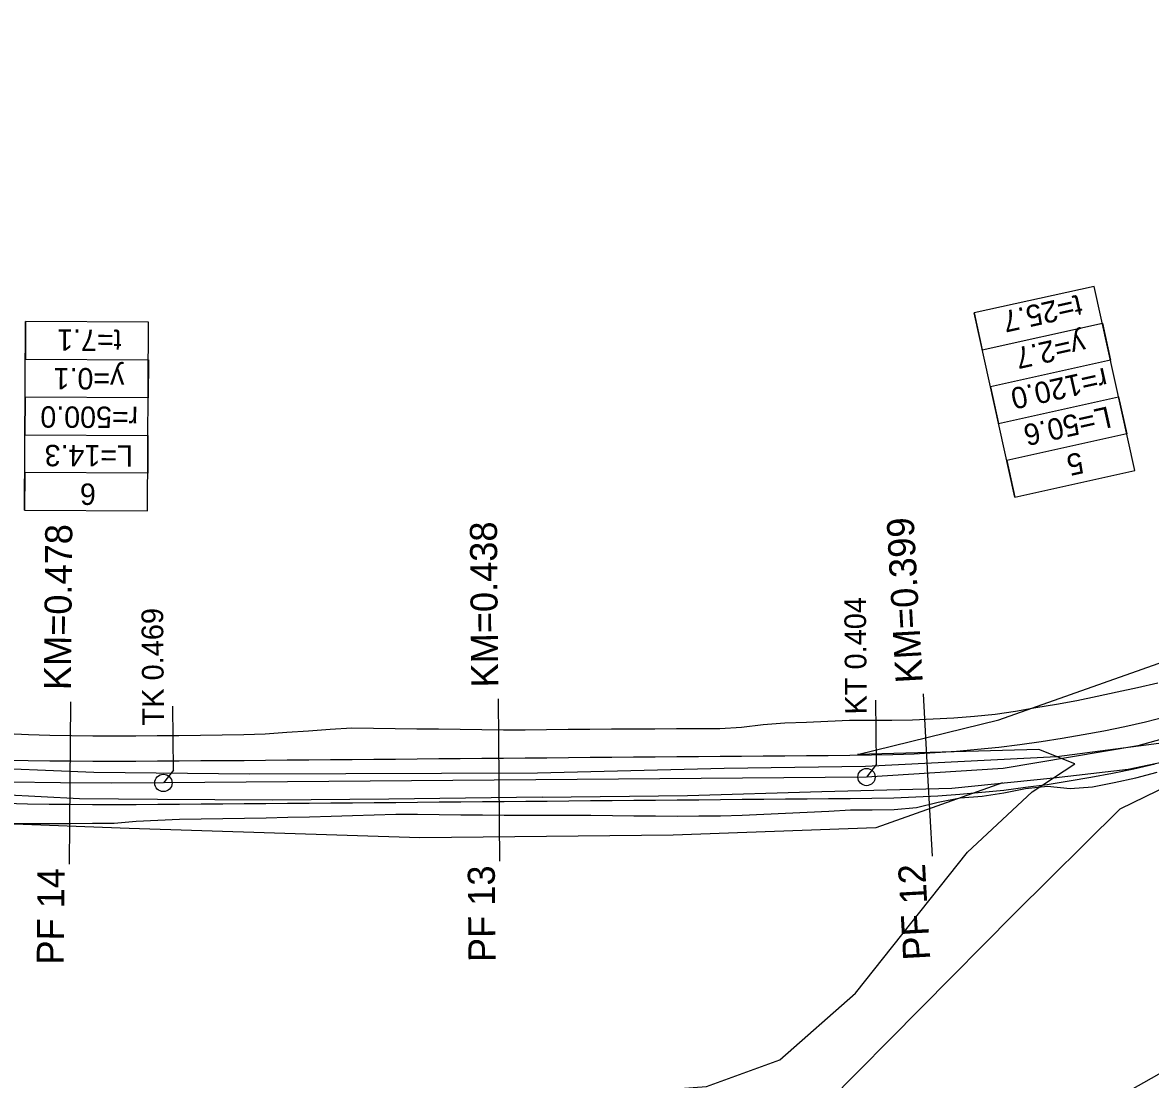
# Model space of a CAD drawing. Extents: x -478000 to -474772, y -1116940 to -1114124.
# Drawn here: x -477710.1 to -477605.9, y -1116669 to -1116571.3 of the extents above; entities that cross this region are included whole.
import ezdxf

# ---------------------------------------------------------------- set-up
doc = ezdxf.new("R2010")
doc.units = 0
for name, color, linetype in [('hrana_P', 7, 'Continuous'), ('L', 7, 'Continuous'), ('POLYGONY_SITUACE_PF', 7, 'Continuous'), ('POLYGONY_SITUACE_PF_POPISY', 7, 'Continuous'), ('POLYGONY_SITUACE_PO', 7, 'Continuous'), ('TABULKY', 7, 'Continuous')]:
    doc.layers.add(name, color=color, linetype=linetype)

msp = doc.modelspace()

# ---------------------------------------------------------------- linework, layer by layer
for points in [[(-477696.15, -1116640.39), (-477696.2, -1116634.49)], [(-477631.17, -1116639.83), (-477631.22, -1116633.94)], [(-477631.17, -1116639.83), (-477632.09, -1116641.03)], [(-477696.15, -1116640.39), (-477697.07, -1116641.58)]]:
    msp.add_lwpolyline(points)
at = {"layer": 'hrana_P'}
for p, q in [((-477607.2, -1116641.11), (-477605.22, -1116640.59)), ((-477617.39, -1116642.08), (-477615.36, -1116641.88)), ((-477615.36, -1116641.88), (-477613.26, -1116642.09)), ((-477613.26, -1116642.09), (-477611.21, -1116641.94)), ((-477611.21, -1116641.94), (-477609.2, -1116641.55)), ((-477609.2, -1116641.55), (-477607.2, -1116641.11)), ((-477625.46, -1116643.35), (-477623.44, -1116642.94)), ((-477623.44, -1116642.94), (-477621.4, -1116642.81)), ((-477621.4, -1116642.81), (-477619.39, -1116642.49)), ((-477619.39, -1116642.49), (-477617.39, -1116642.08)), ((-477631.57, -1116644.07), (-477629.52, -1116644.02)), ((-477629.52, -1116644.02), (-477627.48, -1116643.85)), ((-477627.48, -1116643.85), (-477625.46, -1116643.35)), ((-477701.61, -1116645.28), (-477699.6, -1116645.1)), ((-477699.6, -1116645.1), (-477697.58, -1116645.01)), ((-477697.58, -1116645.01), (-477695.58, -1116644.92)), ((-477695.58, -1116644.92), (-477693.58, -1116644.89)), ((-477693.58, -1116644.89), (-477691.58, -1116644.86)), ((-477691.58, -1116644.86), (-477689.58, -1116644.83)), ((-477689.58, -1116644.83), (-477687.58, -1116644.79)), ((-477687.58, -1116644.79), (-477685.58, -1116644.75)), ((-477685.58, -1116644.75), (-477683.58, -1116644.7)), ((-477683.58, -1116644.7), (-477681.58, -1116644.65)), ((-477681.58, -1116644.65), (-477679.58, -1116644.59)), ((-477679.58, -1116644.59), (-477677.58, -1116644.53)), ((-477677.58, -1116644.53), (-477675.58, -1116644.47)), ((-477675.58, -1116644.47), (-477673.58, -1116644.47)), ((-477673.58, -1116644.47), (-477671.58, -1116644.49)), ((-477671.58, -1116644.49), (-477669.58, -1116644.51)), ((-477669.58, -1116644.51), (-477667.58, -1116644.52)), ((-477667.58, -1116644.52), (-477665.58, -1116644.54)), ((-477665.58, -1116644.54), (-477663.58, -1116644.55)), ((-477663.58, -1116644.55), (-477661.58, -1116644.56)), ((-477661.58, -1116644.56), (-477659.58, -1116644.56)), ((-477659.58, -1116644.56), (-477657.58, -1116644.56)), ((-477657.58, -1116644.56), (-477655.58, -1116644.57)), ((-477655.58, -1116644.57), (-477653.58, -1116644.6)), ((-477653.58, -1116644.6), (-477651.58, -1116644.63)), ((-477651.58, -1116644.63), (-477649.58, -1116644.65)), ((-477649.58, -1116644.65), (-477647.58, -1116644.63)), ((-477647.58, -1116644.63), (-477645.58, -1116644.6)), ((-477645.58, -1116644.6), (-477643.58, -1116644.56)), ((-477643.58, -1116644.56), (-477641.58, -1116644.47)), ((-477641.58, -1116644.47), (-477639.58, -1116644.37)), ((-477639.58, -1116644.37), (-477637.58, -1116644.27)), ((-477637.58, -1116644.27), (-477635.58, -1116644.17)), ((-477635.58, -1116644.17), (-477633.58, -1116644.07)), ((-477633.58, -1116644.07), (-477631.57, -1116644.07)), ((-477711.68, -1116645.29), (-477709.67, -1116645.32)), ((-477709.67, -1116645.32), (-477707.66, -1116645.33)), ((-477707.66, -1116645.33), (-477705.64, -1116645.32)), ((-477705.64, -1116645.32), (-477703.62, -1116645.3)), ((-477703.62, -1116645.3), (-477701.61, -1116645.28))]:
    msp.add_line(p, q, dxfattribs=at)
for points in [[(-477607.04, -1116632.77), (-477605.18, -1116632.33)], [(-477612.66, -1116633.96), (-477610.78, -1116633.57)], [(-477610.78, -1116633.57), (-477608.92, -1116633.17)], [(-477608.92, -1116633.17), (-477607.04, -1116632.77)], [(-477618.32, -1116634.94), (-477616.43, -1116634.62)], [(-477616.43, -1116634.62), (-477614.54, -1116634.3)], [(-477614.54, -1116634.3), (-477612.66, -1116633.96)], [(-477627.85, -1116635.74), (-477625.94, -1116635.66)], [(-477625.94, -1116635.66), (-477624.03, -1116635.55)], [(-477624.03, -1116635.55), (-477622.12, -1116635.4)], [(-477622.12, -1116635.4), (-477620.21, -1116635.22)], [(-477620.21, -1116635.22), (-477618.32, -1116634.94)], [(-477604.39, -1116635.48), (-477606.31, -1116635.95)], [(-477685.65, -1116636.89), (-477683.65, -1116636.75)], [(-477683.65, -1116636.75), (-477681.65, -1116636.6)], [(-477681.65, -1116636.6), (-477679.65, -1116636.49)], [(-477679.65, -1116636.49), (-477677.65, -1116636.52)], [(-477677.65, -1116636.52), (-477675.65, -1116636.54)], [(-477675.65, -1116636.54), (-477673.65, -1116636.57)], [(-477673.65, -1116636.57), (-477671.65, -1116636.59)], [(-477671.65, -1116636.59), (-477669.65, -1116636.61)], [(-477669.65, -1116636.61), (-477667.65, -1116636.64)], [(-477667.65, -1116636.64), (-477665.65, -1116636.66)], [(-477665.65, -1116636.66), (-477663.65, -1116636.66)], [(-477663.65, -1116636.66), (-477661.65, -1116636.63)], [(-477661.65, -1116636.63), (-477659.65, -1116636.61)], [(-477659.65, -1116636.61), (-477657.65, -1116636.6)], [(-477657.65, -1116636.6), (-477655.65, -1116636.59)], [(-477655.65, -1116636.59), (-477653.65, -1116636.58)], [(-477653.65, -1116636.58), (-477651.65, -1116636.57)], [(-477651.65, -1116636.57), (-477649.65, -1116636.56)], [(-477649.65, -1116636.56), (-477647.65, -1116636.55)], [(-477647.65, -1116636.55), (-477645.65, -1116636.54)], [(-477645.65, -1116636.54), (-477643.65, -1116636.41)], [(-477643.65, -1116636.41), (-477641.65, -1116636.18)], [(-477641.65, -1116636.18), (-477639.65, -1116636.03)], [(-477639.65, -1116636.03), (-477637.65, -1116635.95)], [(-477637.65, -1116635.95), (-477635.65, -1116635.87)], [(-477635.65, -1116635.87), (-477633.66, -1116635.79)], [(-477633.66, -1116635.79), (-477631.67, -1116635.79)], [(-477631.67, -1116635.79), (-477629.76, -1116635.78)], [(-477629.76, -1116635.78), (-477627.85, -1116635.74)], [(-477608.22, -1116636.38), (-477610.15, -1116636.78)], [(-477606.31, -1116635.95), (-477608.22, -1116636.38)], [(-477711.52, -1116637.02), (-477709.53, -1116637.09)], [(-477709.53, -1116637.09), (-477707.55, -1116637.16)], [(-477707.55, -1116637.16), (-477705.57, -1116637.21)], [(-477705.57, -1116637.21), (-477703.59, -1116637.23)], [(-477703.59, -1116637.23), (-477701.61, -1116637.23)], [(-477701.61, -1116637.23), (-477699.62, -1116637.22)], [(-477699.62, -1116637.22), (-477697.64, -1116637.2)], [(-477697.64, -1116637.2), (-477695.65, -1116637.18)], [(-477695.65, -1116637.18), (-477693.65, -1116637.15)], [(-477693.65, -1116637.15), (-477691.65, -1116637.12)], [(-477691.65, -1116637.12), (-477689.65, -1116637.09)], [(-477689.65, -1116637.09), (-477687.65, -1116637.03)], [(-477687.65, -1116637.03), (-477685.65, -1116636.89)], [(-477615.96, -1116637.78), (-477617.91, -1116638.05)], [(-477614.02, -1116637.48), (-477615.96, -1116637.78)], [(-477612.08, -1116637.14), (-477614.02, -1116637.48)], [(-477610.15, -1116636.78), (-477612.08, -1116637.14)], [(-477625.74, -1116638.8), (-477627.7, -1116638.91)], [(-477623.78, -1116638.66), (-477625.74, -1116638.8)], [(-477621.82, -1116638.49), (-477623.78, -1116638.66)], [(-477619.86, -1116638.29), (-477621.82, -1116638.49)], [(-477617.91, -1116638.05), (-477619.86, -1116638.29)], [(-477709.57, -1116639.53), (-477711.57, -1116639.49)], [(-477707.58, -1116639.56), (-477709.57, -1116639.53)], [(-477705.59, -1116639.58), (-477707.58, -1116639.56)], [(-477703.6, -1116639.59), (-477705.59, -1116639.58)], [(-477701.61, -1116639.6), (-477703.6, -1116639.59)], [(-477699.61, -1116639.59), (-477701.61, -1116639.6)], [(-477697.62, -1116639.58), (-477699.61, -1116639.59)], [(-477695.62, -1116639.57), (-477697.62, -1116639.58)], [(-477693.62, -1116639.55), (-477695.62, -1116639.57)], [(-477691.63, -1116639.53), (-477693.62, -1116639.55)], [(-477689.62, -1116639.52), (-477691.63, -1116639.53)], [(-477687.62, -1116639.5), (-477689.62, -1116639.52)], [(-477685.63, -1116639.48), (-477687.62, -1116639.5)], [(-477683.62, -1116639.47), (-477685.63, -1116639.48)], [(-477681.62, -1116639.45), (-477683.62, -1116639.47)], [(-477679.63, -1116639.43), (-477681.62, -1116639.45)], [(-477677.63, -1116639.41), (-477679.63, -1116639.43)], [(-477675.63, -1116639.4), (-477677.63, -1116639.41)], [(-477673.63, -1116639.38), (-477675.63, -1116639.4)], [(-477671.63, -1116639.36), (-477673.63, -1116639.38)], [(-477669.63, -1116639.35), (-477671.63, -1116639.36)], [(-477667.63, -1116639.33), (-477669.63, -1116639.35)], [(-477665.63, -1116639.31), (-477667.63, -1116639.33)], [(-477663.63, -1116639.29), (-477665.63, -1116639.31)], [(-477661.63, -1116639.28), (-477663.63, -1116639.29)], [(-477659.63, -1116639.26), (-477661.63, -1116639.28)], [(-477657.63, -1116639.24), (-477659.63, -1116639.26)], [(-477655.63, -1116639.23), (-477657.63, -1116639.24)], [(-477653.63, -1116639.21), (-477655.63, -1116639.23)], [(-477651.63, -1116639.19), (-477653.63, -1116639.21)], [(-477649.63, -1116639.18), (-477651.63, -1116639.19)], [(-477647.63, -1116639.16), (-477649.63, -1116639.18)], [(-477645.63, -1116639.14), (-477647.63, -1116639.16)], [(-477643.63, -1116639.12), (-477645.63, -1116639.14)], [(-477641.63, -1116639.11), (-477643.63, -1116639.12)], [(-477639.63, -1116639.09), (-477641.63, -1116639.11)], [(-477637.63, -1116639.07), (-477639.63, -1116639.09)], [(-477635.63, -1116639.06), (-477637.63, -1116639.07)], [(-477633.63, -1116639.04), (-477635.63, -1116639.06)], [(-477631.64, -1116639.02), (-477633.63, -1116639.04)], [(-477629.67, -1116638.98), (-477631.64, -1116639.02)], [(-477627.7, -1116638.91), (-477629.67, -1116638.98)], [(-477605.4, -1116639.84), (-477607.38, -1116640.29)], [(-477609.37, -1116640.7), (-477611.37, -1116641.08)], [(-477607.38, -1116640.29), (-477609.37, -1116640.7)], [(-477615.38, -1116641.74), (-477617.4, -1116642.01)], [(-477613.37, -1116641.42), (-477615.38, -1116641.74)], [(-477611.37, -1116641.08), (-477613.37, -1116641.42)], [(-477631.59, -1116643.02), (-477633.59, -1116643.04)], [(-477629.55, -1116642.98), (-477631.59, -1116643.02)], [(-477627.52, -1116642.9), (-477629.55, -1116642.98)], [(-477625.49, -1116642.79), (-477627.52, -1116642.9)], [(-477623.46, -1116642.65), (-477625.49, -1116642.79)], [(-477621.44, -1116642.47), (-477623.46, -1116642.65)], [(-477619.41, -1116642.26), (-477621.44, -1116642.47)], [(-477617.4, -1116642.01), (-477619.41, -1116642.26)], [(-477709.64, -1116643.53), (-477711.65, -1116643.49)], [(-477707.63, -1116643.56), (-477709.64, -1116643.53)], [(-477705.62, -1116643.58), (-477707.63, -1116643.56)], [(-477703.62, -1116643.59), (-477705.62, -1116643.58)], [(-477701.61, -1116643.6), (-477703.62, -1116643.59)], [(-477699.6, -1116643.59), (-477701.61, -1116643.6)], [(-477697.59, -1116643.58), (-477699.6, -1116643.59)], [(-477695.59, -1116643.57), (-477697.59, -1116643.58)], [(-477693.59, -1116643.55), (-477695.59, -1116643.57)], [(-477691.59, -1116643.53), (-477693.59, -1116643.55)], [(-477689.59, -1116643.52), (-477691.59, -1116643.53)], [(-477687.59, -1116643.5), (-477689.59, -1116643.52)], [(-477685.59, -1116643.48), (-477687.59, -1116643.5)], [(-477683.59, -1116643.47), (-477685.59, -1116643.48)], [(-477681.59, -1116643.45), (-477683.59, -1116643.47)], [(-477679.59, -1116643.43), (-477681.59, -1116643.45)], [(-477677.59, -1116643.41), (-477679.59, -1116643.43)], [(-477675.59, -1116643.4), (-477677.59, -1116643.41)], [(-477673.59, -1116643.38), (-477675.59, -1116643.4)], [(-477671.59, -1116643.36), (-477673.59, -1116643.38)], [(-477669.59, -1116643.34), (-477671.59, -1116643.36)], [(-477667.59, -1116643.33), (-477669.59, -1116643.34)], [(-477665.59, -1116643.31), (-477667.59, -1116643.33)], [(-477663.59, -1116643.29), (-477665.59, -1116643.31)], [(-477661.59, -1116643.28), (-477663.59, -1116643.29)], [(-477659.59, -1116643.26), (-477661.59, -1116643.28)], [(-477657.59, -1116643.24), (-477659.59, -1116643.26)], [(-477655.59, -1116643.23), (-477657.59, -1116643.24)], [(-477653.59, -1116643.21), (-477655.59, -1116643.23)], [(-477651.59, -1116643.19), (-477653.59, -1116643.21)], [(-477649.59, -1116643.18), (-477651.59, -1116643.19)], [(-477647.59, -1116643.16), (-477649.59, -1116643.18)], [(-477645.59, -1116643.14), (-477647.59, -1116643.16)], [(-477643.59, -1116643.12), (-477645.59, -1116643.14)], [(-477641.59, -1116643.11), (-477643.59, -1116643.12)], [(-477639.59, -1116643.09), (-477641.59, -1116643.11)], [(-477637.59, -1116643.07), (-477639.59, -1116643.09)], [(-477635.59, -1116643.06), (-477637.59, -1116643.07)], [(-477633.59, -1116643.04), (-477635.59, -1116643.06)]]:
    msp.add_lwpolyline(points, dxfattribs=at)
at = {"layer": 'L'}
for points in [[(-477676.54, -1116671.62), (-477664.45, -1116670.94), (-477646.89, -1116669.63), (-477640.09, -1116667.15), (-477633.12, -1116660.99), (-477622.77, -1116647.98), (-477616.79, -1116642.41), (-477612.83, -1116639.8), (-477616.18, -1116638.48), (-477632.92, -1116638.95), (-477619.87, -1116635.76), (-477603.56, -1116630), (-477576.33, -1116620.42), (-477557.94, -1116610.85), (-477539.75, -1116599.77), (-477526.06, -1116586.34), (-477522.74, -1116585.68), (-477521.59, -1116585.23), (-477517.95, -1116584.03), (-477509.86, -1116584.92), (-477494.6, -1116596.02)], [(-477700.31, -1116739.69), (-477690.5, -1116723.45), (-477683.71, -1116707.09), (-477678.38, -1116692.56), (-477674.59, -1116684.86), (-477670.88, -1116680.58), (-477658.29, -1116677.6), (-477644.37, -1116675.5), (-477635.72, -1116671.14), (-477618.42, -1116653.64), (-477608.65, -1116643.96), (-477595.87, -1116637.75), (-477575.19, -1116631.23), (-477562.84, -1116625.57), (-477551.53, -1116618.13), (-477532.47, -1116606.38), (-477522.65, -1116599.53), (-477514.57, -1116596.08), (-477506.14, -1116598.56), (-477494.55, -1116605.15)], [(-477668.01, -1116718.26), (-477656.99, -1116703.29), (-477640, -1116691.72), (-477624.35, -1116679.35), (-477601.22, -1116666.28), (-477577.76, -1116655.91), (-477555.22, -1116642.72), (-477528.71, -1116623.69), (-477520.1, -1116614.5), (-477514.98, -1116618.73), (-477515.34, -1116621.77), (-477532.11, -1116633.75), (-477558.72, -1116651.95), (-477591.14, -1116668.84), (-477604.34, -1116677.55), (-477627.74, -1116697.07), (-477654.41, -1116723.45), (-477661.04, -1116734.56), (-477671.14, -1116741.62)], [(-477662.06, -1116642.88), (-477648.62, -1116642.73), (-477636.21, -1116642.38), (-477624.22, -1116642.06), (-477614.81, -1116641.1), (-477607.9, -1116640.29), (-477600.27, -1116638.71), (-477592.25, -1116636.27), (-477583.05, -1116632.06), (-477573.84, -1116627.24), (-477567.89, -1116624.56), (-477557.66, -1116620.36)], [(-477662.5, -1116640.64), (-477645.24, -1116640.21), (-477632.19, -1116640.04), (-477614.51, -1116639.14), (-477602.96, -1116637.63), (-477593.78, -1116635.03)], [(-477822.04, -1116639.52), (-477820.9, -1116639.08), (-477817.12, -1116638.64), (-477804.89, -1116638.22), (-477790.56, -1116638.04), (-477775.67, -1116638.39), (-477759.07, -1116638.9), (-477743.41, -1116638.91), (-477727.38, -1116639.61), (-477703.51, -1116640.58), (-477689.09, -1116640.74), (-477662.5, -1116640.64)], [(-477662.06, -1116642.88), (-477676.24, -1116643.07), (-477687.02, -1116643.17), (-477697.63, -1116643.1), (-477704.81, -1116643.05), (-477715.49, -1116642.49), (-477726.12, -1116642.26), (-477735.32, -1116641.85), (-477743.53, -1116641.72), (-477756.73, -1116641.03), (-477766.27, -1116640.86), (-477778.45, -1116640.44), (-477788.17, -1116640.01), (-477799.01, -1116640.34), (-477806, -1116640.41), (-477813.11, -1116640.34), (-477819.21, -1116640.7), (-477820.86, -1116641.07), (-477822.31, -1116642.02)], [(-477619.52, -1116641.58), (-477631.23, -1116645.71), (-477649.97, -1116646.39), (-477673.38, -1116646.66), (-477700.23, -1116645.8), (-477732.12, -1116644.58), (-477759.79, -1116644.2), (-477782.63, -1116643.43), (-477804.35, -1116642.53), (-477816.49, -1116642.76), (-477821.58, -1116641.54)]]:
    msp.add_lwpolyline(points, dxfattribs=at)
at = {"layer": 'POLYGONY_SITUACE_PF'}
for points in [[(-477626, -1116648.33), (-477626.41, -1116640.84), (-477626.83, -1116633.36)], [(-477705.76, -1116649.08), (-477705.69, -1116641.58), (-477705.63, -1116634.08)], [(-477665.98, -1116648.81), (-477666.05, -1116641.32), (-477666.11, -1116633.82)]]:
    msp.add_lwpolyline(points, dxfattribs=at)
at = {"layer": 'POLYGONY_SITUACE_PO'}
msp.add_lwpolyline([(-477500.71, -1116571.34), (-477504.22, -1116571.34), (-477507.6, -1116572.28), (-477510.6, -1116574.1), (-477513.01, -1116576.65), (-477523.43, -1116591.17), (-477530, -1116599.19), (-477537.56, -1116606.29), (-477545.97, -1116612.35), (-477555.09, -1116617.27), (-477583.08, -1116630.11), (-477594.83, -1116634.76), (-477607.01, -1116638.16), (-477619.47, -1116640.25), (-477632.09, -1116641.03), (-477697.07, -1116641.58), (-477701.83, -1116641.6), (-477706.59, -1116641.57), (-477711.34, -1116641.5), (-477819.96, -1116639.32)], dxfattribs=at)
for centre in [(-477697.07, -1116641.58), (-477632.09, -1116641.03)]:
    msp.add_circle(centre, 0.8, dxfattribs=at)
at = {"layer": 'TABULKY'}
for points in [[(-477618.38, -1116615.18), (-477622.14, -1116598.16), (-477621.39, -1116601.56), (-477610.29, -1116599.11), (-477609.54, -1116602.52), (-477620.63, -1116604.98), (-477619.88, -1116608.38), (-477608.79, -1116605.92), (-477608.03, -1116609.32), (-477619.13, -1116611.78), (-477618.38, -1116615.18), (-477607.28, -1116612.72), (-477611.04, -1116595.72), (-477622.14, -1116598.16)], [(-477709.9, -1116616.38), (-477709.81, -1116598.95), (-477709.82, -1116602.43), (-477698.46, -1116602.49), (-477698.48, -1116605.99), (-477709.84, -1116605.93), (-477709.86, -1116609.41), (-477698.5, -1116609.47), (-477698.52, -1116612.95), (-477709.88, -1116612.89), (-477709.9, -1116616.38), (-477698.53, -1116616.44), (-477698.44, -1116599.02), (-477709.81, -1116598.95)]]:
    msp.add_lwpolyline(points, dxfattribs=at)

# ---------------------------------------------------------------- texts
for s, height, rotation, p in [('t=25.7', 1.976, 192.5625, (-477612.43, -1116596.44)), ('t=7.1', 1.976, 179.6702, (-477700.93, -1116599.71)), ('y=2.7', 1.976, 192.5625, (-477612.11, -1116600.01)), ('y=0.1', 1.976, 179.6702, (-477700.67, -1116603.27)), ('r=120.0', 1.976, 192.5625, (-477610.08, -1116603.2)), ('r=500.0', 1.976, 179.6702, (-477699.4, -1116606.83)), ('L=50.6', 1.976, 192.5625, (-477609.75, -1116606.77)), ('L=14.3', 1.976, 179.6702, (-477699.88, -1116610.39)), ('5', 1.98, 192.5625, (-477612.3, -1116610.99)), ('6', 1.98, 179.6702, (-477703.3, -1116613.92)), ('KT 0.404', 2, 90.488, (-477632.06, -1116635.25)), ('TK 0.469', 2, 90.488, (-477697.01, -1116636.26))]:
    msp.add_text(s, height=height, rotation=rotation).set_placement(p)
at = {"layer": 'POLYGONY_SITUACE_PF_POPISY'}
for s, rotation, p in [('KM=0.478', 89.5001, (-477705.62, -1116633.01)), ('KM=0.438', 90.488, (-477666.12, -1116632.75)), ('KM=0.399', 93.1979, (-477626.89, -1116632.29)), ('PF 12', 93.1979, (-477626.19, -1116657.89)), ('PF 14', 89.5001, (-477706.28, -1116658.37)), ('PF 13', 90.488, (-477666.37, -1116658.11))]:
    msp.add_text(s, height=2.5, rotation=rotation, dxfattribs=at).set_placement(p)

doc.saveas('drawing.dxf')
